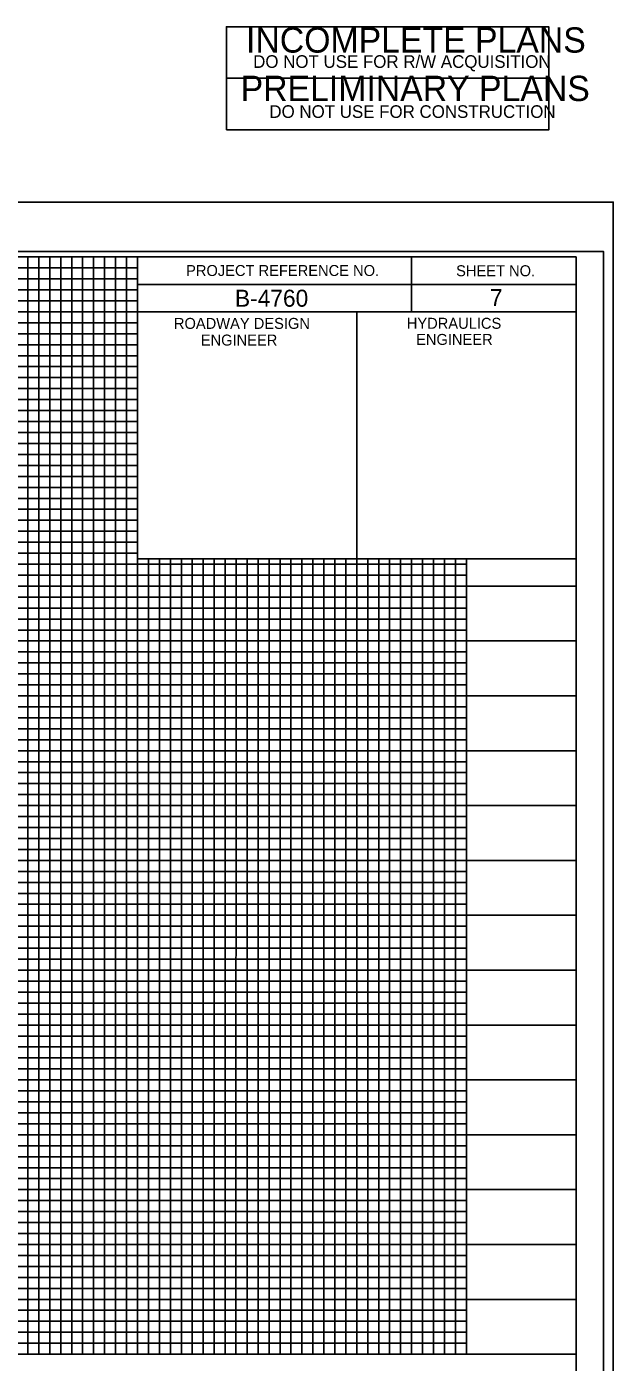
# Model space of a CAD drawing. Extents: x 570622 to 580296, y -55533 to -48575.
# Drawn here: x 572038 to 572306, y -54411 to -53803 of the extents above; entities that cross this region are included whole.
import ezdxf

# ---------------------------------------------------------------- set-up
doc = ezdxf.new("R2010")
doc.units = 0
for name, color, linetype in [('Sheet Cutting Line CELL', 7, 'Continuous'), ('Sheet Data Field CELL', 7, 'Continuous'), ('Sheet DOT Grid CELL', 7, 'Continuous'), ('Sheet Layout Profile Border Port 1', 7, 'Continuous'), ('Sheet Plot Border Inside CELL', 7, 'Continuous'), ('Sheet Plot Border Outside CELL', 7, 'Continuous'), ('Sheet Profile CELL', 7, 'Continuous'), ('Sheet Profile Grid Major CELL', 7, 'Continuous'), ('Sheet Profile Grid Middle CELL', 7, 'Continuous'), ('Sheet Profile Grid Minor CELL', 7, 'Continuous'), ('Sheet Sticker Incomplete CELL', 7, 'Continuous'), ('Sheet Sticker Preliminary CELL', 7, 'Continuous')]:
    doc.layers.add(name, color=color, linetype=linetype)

msp = doc.modelspace()

# ---------------------------------------------------------------- linework, layer by layer
at = {"layer": 'Sheet Cutting Line CELL'}
msp.add_line((572305.69, -53882.69), (570621.69, -53882.69), dxfattribs=at)
at = {"layer": 'Sheet DOT Grid CELL'}
for p, q in [((572038.69, -54407.69), (572038.69, -53907.69)), ((572088.64, -53957.69), (570788.69, -53957.69)), ((572088.64, -54007.69), (570788.69, -54007.69)), ((572088.69, -54407.69), (572088.69, -54045.24)), ((572138.69, -54407.69), (572138.69, -54045.24)), ((572188.69, -54407.69), (572188.69, -54045.24)), ((572238.69, -54407.69), (572238.69, -54045.24)), ((572288.69, -54057.69), (570788.69, -54057.69)), ((572288.69, -54107.69), (570788.69, -54107.69)), ((572288.69, -54157.69), (570788.69, -54157.69)), ((572288.69, -54207.69), (570788.69, -54207.69)), ((572288.69, -54257.69), (570788.69, -54257.69)), ((572288.69, -54307.69), (570788.69, -54307.69)), ((572288.69, -54357.69), (570788.69, -54357.69))]:
    msp.add_line(p, q, dxfattribs=at)
at = {"layer": 'Sheet Layout Profile Border Port 1'}
msp.add_lwpolyline([(570838.69, -53907.69), (570838.69, -54407.69), (572238.69, -54407.69), (572238.69, -54045.24), (572088.64, -54045.24), (572088.64, -53907.69)], close=True, dxfattribs=at)
at = {"layer": 'Sheet Plot Border Inside CELL'}
msp.add_lwpolyline([(570634.69, -54960.24), (572301.19, -54960.24), (572301.19, -53905.14), (570634.69, -53905.14)], close=True, dxfattribs=at)
at = {"layer": 'Sheet Plot Border Outside CELL'}
msp.add_lwpolyline([(570621.69, -54982.69), (572305.69, -54982.69), (572305.69, -53882.69), (570621.69, -53882.69)], close=True, dxfattribs=at)
at = {"layer": 'Sheet Profile CELL'}
for p, q in [((572213.69, -53907.74), (572213.69, -53932.74)), ((572088.64, -53920.24), (572288.69, -53920.24)), ((572188.69, -53932.74), (572188.69, -54045.19)), ((570788.69, -54407.69), (572288.69, -54407.69))]:
    msp.add_line(p, q, dxfattribs=at)
for points in [[(572288.69, -53907.69), (570788.69, -53907.69), (570788.69, -54957.69), (572288.69, -54957.69)], [(572088.64, -53907.69), (572288.69, -53907.69), (572288.69, -53932.74), (572088.64, -53932.74)], [(572088.64, -53932.74), (572188.69, -53932.74), (572188.69, -54045.24), (572088.64, -54045.24)], [(572188.69, -53932.74), (572288.69, -53932.74), (572288.69, -54045.24), (572188.69, -54045.24)]]:
    msp.add_lwpolyline(points, close=True, dxfattribs=at)
at = {"layer": 'Sheet Profile Grid Major CELL'}
for points in [[(571538.69, -54407.69), (571588.69, -54407.69), (571588.69, -53907.69), (571638.69, -53907.69), (571638.69, -54407.69), (571688.69, -54407.69), (571688.69, -53907.69), (571738.69, -53907.69), (571738.69, -54407.69), (571788.69, -54407.69), (571788.69, -53907.69), (571838.69, -53907.69), (571838.69, -54407.69), (571888.69, -54407.69), (571888.69, -53907.69), (571938.69, -53907.69), (571938.69, -54407.69), (571988.69, -54407.69), (571988.69, -53907.69), (572038.69, -53907.69), (572038.69, -54407.69), (572088.69, -54407.69), (572088.69, -53907.69), (572114.99, -53907.69)], [(570788.69, -53957.69), (572088.69, -53957.69)], [(572088.69, -54007.69), (570788.69, -54007.69), (570788.69, -54057.69), (572288.69, -54057.69)], [(572138.69, -54045.24), (572138.69, -54407.69), (572188.69, -54407.69), (572188.69, -54407.69), (572188.69, -54045.24)], [(572238.69, -54045.24), (572238.69, -54407.69), (572288.69, -54407.69), (572288.69, -54057.69)], [(572288.69, -54107.69), (570788.69, -54107.69), (570788.69, -54157.69), (572288.69, -54157.69)], [(572288.69, -54207.69), (570788.69, -54207.69), (570788.69, -54257.69), (572288.69, -54257.69)], [(572288.69, -54307.69), (570788.69, -54307.69), (570788.69, -54307.69), (570788.69, -54357.69), (572288.69, -54357.69)]]:
    msp.add_lwpolyline(points, dxfattribs=at)
at = {"layer": 'Sheet Profile Grid Middle CELL'}
msp.add_line((570788.69, -53932.69), (572088.64, -53932.69), dxfattribs=at)
for points in [[(571563.69, -54407.69), (571613.69, -54407.69), (571613.69, -53907.69), (571663.69, -53907.69), (571663.69, -54407.69), (571713.69, -54407.69), (571713.69, -53907.69), (571763.69, -53907.69), (571763.69, -54407.69), (571813.69, -54407.69), (571813.69, -53907.69), (571863.69, -53907.69), (571863.69, -54407.69), (571913.69, -54407.69), (571913.69, -53907.69), (571963.69, -53907.69), (571963.69, -54407.69), (572013.69, -54407.69), (572013.69, -53907.69), (572063.69, -53907.69), (572063.69, -54407.69), (572113.69, -54407.69), (572113.69, -54045.24)], [(572088.69, -53982.69), (570788.69, -53982.69), (570788.69, -54032.69), (572088.69, -54032.69)], [(572113.69, -54144.89), (572113.69, -54407.69), (572163.69, -54407.69), (572163.69, -54045.24)], [(572163.69, -54144.89), (572163.69, -54407.69), (572213.69, -54407.69), (572213.69, -54045.24)], [(572288.69, -54082.69), (570788.69, -54082.69), (570788.69, -54132.69), (572113.69, -54132.69)], [(572113.69, -54132.69), (572288.69, -54132.69)], [(572288.69, -54182.69), (570788.69, -54182.69), (570788.69, -54232.69), (572288.69, -54232.69)], [(572288.69, -54282.69), (570788.69, -54282.69), (570788.69, -54332.69), (572288.69, -54332.69)], [(572288.69, -54382.69), (570788.69, -54382.69)]]:
    msp.add_lwpolyline(points, dxfattribs=at)
at = {"layer": 'Sheet Profile Grid Minor CELL'}
for p, q in [((570838.69, -53912.69), (572088.69, -53912.69)), ((572088.69, -53917.69), (570838.69, -53918.04)), ((570838.69, -53922.69), (572088.69, -53922.69)), ((572088.64, -54042.69), (570838.69, -54042.69)), ((572238.69, -54047.69), (570838.69, -54047.69)), ((572238.69, -54052.69), (570838.69, -54052.69)), ((570838.69, -54062.69), (572238.69, -54062.69)), ((572238.69, -54067.69), (570838.69, -54067.69)), ((570838.69, -54072.69), (572238.69, -54072.69)), ((572238.69, -54092.69), (570838.69, -54092.69)), ((570838.69, -54097.69), (572238.69, -54097.69)), ((572238.69, -54117.69), (570838.69, -54117.69)), ((570838.69, -54122.69), (572238.69, -54122.69)), ((572238.69, -54142.69), (570838.69, -54142.69)), ((570838.69, -54147.69), (572238.69, -54147.69)), ((572238.69, -54152.69), (570838.69, -54152.69)), ((570838.69, -54162.69), (572238.69, -54162.69)), ((572238.69, -54167.69), (570838.69, -54167.69)), ((570838.69, -54172.69), (572238.69, -54172.69)), ((572238.69, -54177.69), (570838.69, -54177.69)), ((570838.69, -54187.69), (572238.69, -54187.69)), ((572238.69, -54192.69), (570838.69, -54192.69)), ((570838.69, -54197.69), (572238.69, -54197.69)), ((572238.69, -54202.69), (570838.69, -54202.69)), ((570838.69, -54212.69), (572238.69, -54212.69)), ((572238.69, -54217.69), (570838.69, -54217.69)), ((570838.69, -54222.69), (572238.69, -54222.69)), ((572238.69, -54227.69), (570838.69, -54227.69)), ((570838.69, -54237.69), (572238.69, -54237.69)), ((572238.69, -54242.69), (570838.69, -54242.69)), ((570838.69, -54247.69), (572238.69, -54247.69)), ((572238.69, -54252.69), (570838.69, -54252.69)), ((570838.69, -54262.69), (572238.69, -54262.69)), ((572238.69, -54267.69), (570838.69, -54267.69)), ((570838.69, -54272.69), (572238.69, -54272.69)), ((572238.69, -54277.69), (570838.69, -54277.69)), ((570838.69, -54287.69), (572238.69, -54287.69)), ((572238.69, -54292.69), (570838.69, -54292.69)), ((572238.69, -54297.69), (570838.69, -54297.69)), ((572238.69, -54302.69), (570838.69, -54302.69)), ((570838.69, -54312.69), (572238.69, -54312.69)), ((572238.69, -54317.69), (570838.69, -54317.69)), ((570838.69, -54322.69), (572238.69, -54322.69)), ((572238.69, -54327.69), (570838.69, -54327.69)), ((570838.69, -54337.69), (572238.69, -54337.69)), ((572238.69, -54342.69), (570838.69, -54342.69)), ((570838.69, -54347.69), (572238.69, -54347.69)), ((572238.69, -54352.69), (570838.69, -54352.69)), ((570838.69, -54362.69), (572238.69, -54362.69)), ((572238.69, -54367.69), (570838.69, -54367.69)), ((570838.69, -54372.69), (572238.69, -54372.69)), ((572238.69, -54377.69), (570838.69, -54377.69)), ((570838.69, -54387.69), (572238.69, -54387.69)), ((572238.69, -54392.69), (570838.69, -54392.69)), ((570838.69, -54397.69), (572238.69, -54397.69))]:
    msp.add_line(p, q, dxfattribs=at)
for points in [[(572033.69, -53907.69), (572043.69, -53907.69), (572043.69, -54407.69), (572048.69, -54407.69), (572048.69, -53907.69), (572053.69, -53907.69), (572053.69, -54407.69), (572058.69, -54407.69), (572058.69, -53907.69), (572068.69, -53907.69), (572068.69, -54407.69), (572073.69, -54407.69), (572073.69, -53907.69), (572078.69, -53907.69), (572078.69, -54407.69), (572083.69, -54407.69), (572083.69, -53907.69), (572093.69, -53907.69)], [(572088.69, -53927.69), (570838.69, -53927.69), (570838.69, -53937.69), (572088.69, -53937.69)], [(572088.64, -53942.69), (570838.69, -53942.69), (570838.69, -53947.69), (572088.69, -53947.69)], [(572088.69, -53952.69), (570838.69, -53952.69), (570838.69, -53962.69), (572088.69, -53962.69)], [(572088.69, -53967.69), (570838.69, -53967.69), (570838.69, -53972.69), (572088.69, -53972.69)], [(572088.69, -53977.69), (570838.69, -53977.69), (570838.69, -53987.69), (572088.69, -53987.69)], [(572088.69, -53992.69), (570838.69, -53992.69), (570838.69, -53997.69), (572088.69, -53997.69)], [(572088.69, -54002.69), (570838.69, -54002.69), (570838.69, -54012.69), (572088.69, -54012.69)], [(572088.69, -54017.79), (570838.79, -54017.79), (570838.79, -54022.69), (572088.69, -54022.69)], [(572088.69, -54027.69), (570838.69, -54027.69), (570838.69, -54037.69), (572088.69, -54037.69)], [(572093.69, -54045.24), (572093.69, -54407.69), (572098.69, -54407.69), (572098.69, -54045.24)], [(572103.69, -54045.24), (572103.69, -54407.69), (572108.69, -54407.69), (572108.69, -54045.24)], [(572118.69, -54045.24), (572118.69, -54407.69), (572118.69, -54407.69), (572123.69, -54407.69), (572128.69, -54407.69), (572128.69, -54045.24)], [(572123.69, -54045.24), (572123.69, -54407.69)], [(572133.69, -54045.24), (572133.59, -54407.64), (572138.59, -54407.64), (572143.69, -54407.69), (572143.69, -54045.24)], [(572143.69, -54144.89), (572143.69, -54407.69), (572148.69, -54407.69), (572148.69, -54045.24)], [(572153.69, -54045.24), (572153.69, -54407.69), (572158.69, -54407.69), (572158.69, -54045.24)], [(572168.69, -54045.24), (572168.69, -54407.69), (572173.69, -54407.69), (572173.69, -54045.24)], [(572178.69, -54045.24), (572178.69, -54407.69), (572183.69, -54407.69), (572183.69, -54045.24)], [(572193.69, -54045.24), (572193.69, -54407.69), (572198.69, -54407.69), (572198.69, -54045.24)], [(572203.69, -54045.24), (572203.69, -54407.69), (572208.69, -54407.69), (572208.69, -54045.24)], [(572218.69, -54045.24), (572218.69, -54407.69), (572223.69, -54407.69), (572223.69, -54045.24)], [(572228.69, -54045.24), (572228.69, -54407.69), (572233.69, -54407.69), (572233.69, -54045.24)], [(572238.69, -54077.69), (570838.69, -54077.69), (570838.69, -54087.69), (572238.69, -54087.69)], [(572238.69, -54102.69), (570838.69, -54102.69), (570838.69, -54112.69), (572238.69, -54112.69)], [(572238.69, -54127.69), (570838.69, -54127.69), (570838.69, -54137.69), (572238.69, -54137.69)], [(572238.69, -54402.69), (570838.69, -54402.69)]]:
    msp.add_lwpolyline(points, dxfattribs=at)
at = {"layer": 'Sheet Sticker Incomplete CELL'}
msp.add_lwpolyline([(572129.24, -53826.29), (572129.24, -53802.79), (572276.24, -53802.79), (572276.24, -53826.29)], close=True, dxfattribs=at)
at = {"layer": 'Sheet Sticker Preliminary CELL'}
msp.add_lwpolyline([(572129.24, -53849.79), (572129.24, -53826.29), (572276.24, -53826.29), (572276.24, -53849.79)], close=True, dxfattribs=at)

# ---------------------------------------------------------------- texts
at = {"layer": 'Sheet Data Field CELL'}
for s, p in [('B-4760', (572133.14, -53930.38)), ('7', (572249.43, -53930.08))]:
    msp.add_text(s, height=7.75, dxfattribs=at).set_placement(p)
at = {"layer": 'Sheet Profile CELL'}
for s, height, p in [('PROJECT REFERENCE NO.', 5.0001, (572110.85, -53916.38)), ('SHEET NO.', 5, (572234, -53916.48)), ('ROADWAY DESIGN', 5.0001, (572105.3, -53940.48)), ('HYDRAULICS', 5, (572211.5, -53940.43)), ('ENGINEER', 5, (572117.55, -53948.08)), ('ENGINEER', 5, (572215.75, -53947.78))]:
    msp.add_text(s, height=height, dxfattribs=at).set_placement(p)
at = {"layer": 'Sheet Sticker Incomplete CELL'}
for s, height, p in [('INCOMPLETE PLANS', 11.52, (572138.19, -53814.59)), ('DO NOT USE FOR R/W ACQUISITION', 5.76, (572141.44, -53821.54))]:
    msp.add_text(s, height=height, dxfattribs=at).set_placement(p)
at = {"layer": 'Sheet Sticker Preliminary CELL'}
for s, height, p in [('PRELIMINARY PLANS', 11.52, (572135.74, -53836.64)), ('DO NOT USE FOR CONSTRUCTION', 5.76, (572148.84, -53844.34))]:
    msp.add_text(s, height=height, dxfattribs=at).set_placement(p)

doc.saveas('drawing.dxf')
